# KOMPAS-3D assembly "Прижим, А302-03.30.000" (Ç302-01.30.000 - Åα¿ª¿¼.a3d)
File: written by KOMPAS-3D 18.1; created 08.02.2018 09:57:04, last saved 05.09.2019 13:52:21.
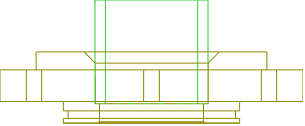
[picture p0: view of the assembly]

Document properties: Автор: Милов; Полное имя файла: D:\Мембранные насосы\Мембранный электропривод\А302-00.00.000 - ASTRA-302 (МЭ200)\3Д ПВХ\А302-01.30.000 - Прижим.a3d

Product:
- Part/product: Прижим  | designation А302-03.30.000  | pos. 0
    Материал: Полиамид П-12Б-20  ТУ 6-05-898-73 (density 1020 kg/m3)
    Масса: 0.245979
    Раздел спецификации: Сборочные единицы
    Форматы листов документа: A3
    source file: ..\Чертежи Полипропилен\А302-03.30.000 - Прижим.cdw
  - Component [detail]: Труба 50 PN10 S=4,6 FV PPR ф. FV PLAST  | designation 01  | pos. 4  | Материал: Полипропилен  ГОСТ 26996-86 (density 900 kg/m3); Масса: 0.0271621; Раздел спецификации: Прочие изделия; Примечание: м; source file: ..\..\..\..\1 ПКИ 3D\Полипропиленовые фитинги, трубы\Трубы\Труба 50 PN10 S=4,6 FV PPR ф. FV PLAST.m3d
  - Component [detail]: Прижим  | designation А302-03.30.001  | pos. 1  | Масса: 0.218817; Раздел спецификации: Детали; Форматы листов документа: A4; source file: А302-01.30.001 - Прижим.m3d
- Part/product: Прижим  | designation А302-01.30.000  | pos. 0
    Материал: Полиамид П-12Б-20  ТУ 6-05-898-73 (density 1020 kg/m3)
    Масса: 0.266873
    Раздел спецификации: Сборочные единицы
    Форматы листов документа: A3
    source file: А302-01.30.000 - Прижим.cdw
  - Component [detail]: Труба ПВХ PN10 50х2,4  | pos. 4  | Масса: 0.340305; Раздел спецификации: Прочие изделия; Примечание: мм; source file: Отработка\Труба ПВХ PN10 50х2,4.m3d
  - Component [detail]: Прижим  | designation А302-01.30.001  | pos. 1  | Масса: 0.21871; Раздел спецификации: Детали; Форматы листов документа: A4; source file: А302-01.30.001 - Прижим.cdw, А302-01.30.001 - Прижим.m3d

Referenced files in D:\Мембранные насосы\Мембранный электропривод\А302-00.00.000 - ASTRA-302 (МЭ200)\3Д ПВХ\: А302-01.30.001 - Прижим.m3d, А302-01.30.001 - Прижим.cdw, А302-01.30.000 - Прижим.cdw
Referenced files in D:\1 ПКИ 3D\Полипропиленовые фитинги, трубы\Трубы\: Труба 50 PN10 S=4,6 FV PPR ф. FV PLAST.m3d
Referenced files in D:\Мембранные насосы\Мембранный электропривод\А302-00.00.000 - ASTRA-302 (МЭ200)\3Д ПВХ\Отработка\: Труба ПВХ PN10 50х2,4.m3d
